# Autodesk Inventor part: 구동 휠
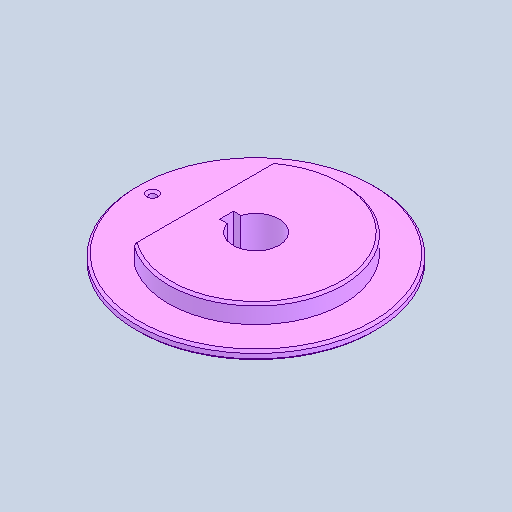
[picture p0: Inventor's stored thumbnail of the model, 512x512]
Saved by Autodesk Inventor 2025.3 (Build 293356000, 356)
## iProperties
Created: 2025-09
Part Number: 구동 휠
Material: 강철, 연강
Document SubType Name: Modeling
Designer: PC-15
Density: 7.85 g/cm^3
Appearance: 기본값
Author: jhkim
Sending System: Autodesk Inventor 2026
Preprocessor: ST-DEVELOPER v20.1
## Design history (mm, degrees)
feature "솔리드1"
node "솔리드2"
